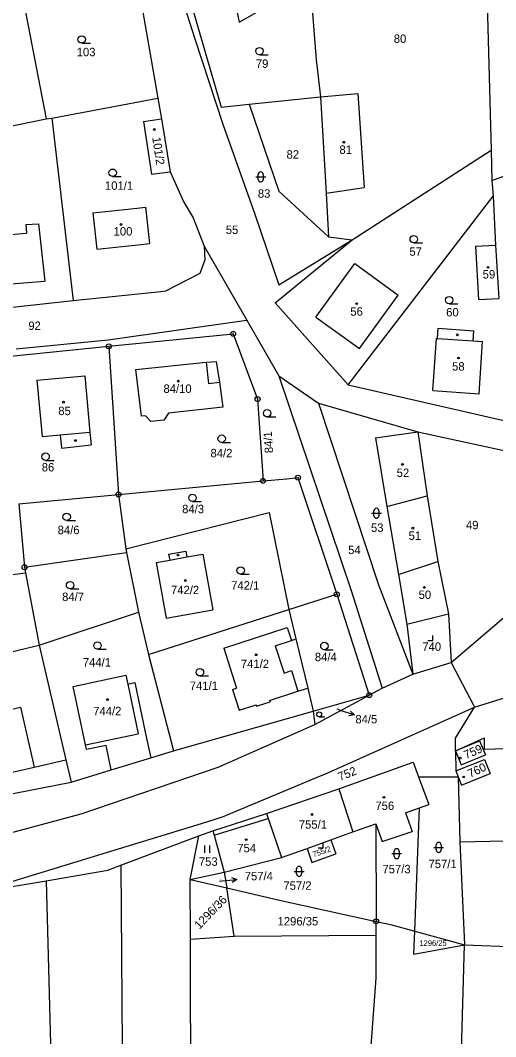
# Model space of a CAD drawing. Extents: x -779596 to -776743, y -1030330 to -1024513.
# Drawn here: x -778185.6 to -778089.5, y -1025062.8 to -1024857.5 of the extents above; entities that cross this region are included whole.
import ezdxf

# ---------------------------------------------------------------- set-up
doc = ezdxf.new("R2010")
doc.units = 0
for name, color, linetype in [('hranice parcel', 7, 'Continuous'), ('hranice vnitřní', 7, 'Continuous'), ('kultura', 7, 'Continuous'), ('Kód', 7, 'Continuous'), ('č_ parcel šipka', 7, 'Continuous'), ('č_pacel stav_', 7, 'Continuous'), ('č_parcel poz_', 7, 'Continuous')]:
    doc.layers.add(name, color=color, linetype=linetype)

msp = doc.modelspace()

# ---------------------------------------------------------------- linework, layer by layer
at = {"layer": 'hranice parcel'}
for points in [[(-778091.74, -1024836.72), (-778090.46, -1024883.74)], [(-778187.93, -1024838.01), (-778180.36, -1024877.36)], [(-778156.76, -1024840.95), (-778150.3, -1024861.21)], [(-778143.11, -1024849.44), (-778141.34, -1024857.84)], [(-778141.34, -1024857.84), (-778129.56, -1024851.15)], [(-778126.92, -1024850.83), (-778125.81, -1024865.47)], [(-778160.91, -1024855.45), (-778157.79, -1024873.21)], [(-778150.99, -1024854.44), (-778145, -1024875.04)], [(-778150.3, -1024861.21), (-778144.64, -1024878.44)], [(-778125.81, -1024865.47), (-778124.94, -1024872.91)], [(-778179.21, -1024877.22), (-778157.79, -1024873.21)], [(-778157.79, -1024873.21), (-778157.06, -1024877.35)], [(-778139.35, -1024874.44), (-778124.94, -1024872.91)], [(-778124.94, -1024872.91), (-778117.34, -1024872.25)], [(-778124.94, -1024872.91), (-778123.8, -1024892.38)], [(-778117.34, -1024872.25), (-778116.08, -1024891.25)], [(-778145, -1024875.04), (-778139.35, -1024874.44)], [(-778139.35, -1024874.44), (-778133.3, -1024892.02)], [(-778200.17, -1024881.44), (-778180.36, -1024877.36)], [(-778180.36, -1024877.36), (-778179.21, -1024877.22)], [(-778179.21, -1024877.22), (-778174.88, -1024914.1)], [(-778160.66, -1024877.95), (-778157.06, -1024877.35)], [(-778160.66, -1024877.95), (-778159.06, -1024888.53)], [(-778157.06, -1024877.35), (-778155.28, -1024888.07)], [(-778144.64, -1024878.44), (-778138.18, -1024896.63)], [(-778118.52, -1024901.85), (-778090.46, -1024883.74)], [(-778090.46, -1024883.74), (-778090.29, -1024889.82)], [(-778090.29, -1024889.82), (-778074.2, -1024884)], [(-778159.06, -1024888.53), (-778155.28, -1024888.07)], [(-778155.28, -1024888.07), (-778152.54, -1024894.21)], [(-778090.29, -1024889.82), (-778090.05, -1024892.99)], [(-778133.3, -1024892.02), (-778123.28, -1024901.22)], [(-778123.8, -1024892.38), (-778116.08, -1024891.25)], [(-778123.8, -1024892.38), (-778123.28, -1024901.22)], [(-778152.54, -1024894.21), (-778150.62, -1024897.36)], [(-778119.3, -1024931.13), (-778090.05, -1024892.99)], [(-778090.05, -1024892.99), (-778089.57, -1024902.87)], [(-778170.92, -1024896.37), (-778161.93, -1024895.39)], [(-778170.92, -1024896.37), (-778170.12, -1024903.72)], [(-778161.93, -1024895.39), (-778160.28, -1024895.21)], [(-778160.28, -1024895.21), (-778159.49, -1024902.57)], [(-778138.18, -1024896.63), (-778133.35, -1024910.93)], [(-778184.42, -1024898.72), (-778181.87, -1024898.56)], [(-778184.42, -1024898.72), (-778184.29, -1024900.49)], [(-778181.87, -1024898.56), (-778180.62, -1024910.17)], [(-778150.62, -1024897.36), (-778148.41, -1024903.12)], [(-778193.8, -1024901.26), (-778184.29, -1024900.49)], [(-778170.12, -1024903.72), (-778161.13, -1024902.74)], [(-778161.13, -1024902.74), (-778159.49, -1024902.57)], [(-778134.1, -1024914.57), (-778118.52, -1024901.85)], [(-778133.35, -1024910.93), (-778118.52, -1024901.85)], [(-778123.28, -1024901.22), (-778118.52, -1024901.85)], [(-778093.62, -1024903.12), (-778089.57, -1024902.87)], [(-778089.57, -1024902.87), (-778088.9, -1024913.65)], [(-778148.41, -1024903.12), (-778139.8, -1024918.03)], [(-778148.41, -1024903.12), (-778148.29, -1024906)], [(-778093.62, -1024903.12), (-778092.96, -1024913.9)], [(-778149.21, -1024908.52), (-778148.29, -1024906)], [(-778125.84, -1024917.43), (-778118.01, -1024906.61)], [(-778118.01, -1024906.61), (-778109.22, -1024912.97)], [(-778156.15, -1024912.15), (-778149.21, -1024908.52)], [(-778192.67, -1024911.14), (-778180.62, -1024910.17)], [(-778174.88, -1024914.1), (-778159.12, -1024912.45)], [(-778159.12, -1024912.45), (-778157.19, -1024912.26)], [(-778157.19, -1024912.26), (-778156.15, -1024912.15)], [(-778117.05, -1024923.79), (-778109.22, -1024912.97)], [(-778197.06, -1024916.48), (-778174.88, -1024914.1)], [(-778134.1, -1024914.57), (-778119.3, -1024931.13)], [(-778092.96, -1024913.9), (-778088.9, -1024913.65)], [(-778167.81, -1024922.02), (-778140.35, -1024918.11)], [(-778140.35, -1024918.11), (-778139.8, -1024918.03)], [(-778139.8, -1024918.03), (-778133.3, -1024929.3)], [(-778125.84, -1024917.43), (-778117.05, -1024923.79)], [(-778167.67, -1024923.32), (-778142.57, -1024920.8)], [(-778142.57, -1024920.8), (-778137.62, -1024933.98)], [(-778101.29, -1024921.75), (-778101.15, -1024919.68)], [(-778101.15, -1024919.68), (-778093.95, -1024920.22)], [(-778094.09, -1024922.25), (-778093.95, -1024920.22)], [(-778187.57, -1024925.32), (-778167.67, -1024923.32)], [(-778186.38, -1024923.83), (-778167.81, -1024922.02)], [(-778167.67, -1024923.32), (-778165.74, -1024953.24)], [(-778102.21, -1024932.25), (-778101.49, -1024921.74)], [(-778101.49, -1024921.74), (-778101.29, -1024921.75)], [(-778094.09, -1024922.25), (-778092.16, -1024922.38)], [(-778092.88, -1024932.89), (-778092.16, -1024922.38)], [(-778162.25, -1024928.04), (-778148, -1024926.51)], [(-778148, -1024926.51), (-778145.96, -1024926.41)], [(-778145.96, -1024926.41), (-778145.32, -1024930.56)], [(-778182.21, -1024930.16), (-778172.55, -1024929.26)], [(-778172.55, -1024929.26), (-778171.5, -1024940.65)], [(-778161.1, -1024937.44), (-778162.25, -1024928.04)], [(-778133.3, -1024929.3), (-778125.29, -1024934.81)], [(-778133.3, -1024929.3), (-778118.73, -1024972.64)], [(-778182.21, -1024930.16), (-778181.15, -1024941.54)], [(-778145.32, -1024930.56), (-778144.66, -1024935.59)], [(-778119.3, -1024931.13), (-778087.28, -1024938.46)], [(-778102.21, -1024932.25), (-778092.88, -1024932.89)], [(-778144.66, -1024935.59), (-778155.62, -1024936.85)], [(-778137.62, -1024933.98), (-778136.53, -1024950.51)], [(-778125.29, -1024934.81), (-778113.21, -1024971.52)], [(-778125.29, -1024934.81), (-778105.25, -1024940.59)], [(-778160.25, -1024937.35), (-778161.1, -1024937.44)], [(-778159.17, -1024938.53), (-778160.25, -1024937.35)], [(-778155.62, -1024936.85), (-778156.58, -1024938.23)], [(-778156.58, -1024938.23), (-778159.17, -1024938.53)], [(-778181.15, -1024941.54), (-778177.51, -1024941.21)], [(-778177.51, -1024941.21), (-778177.25, -1024943.91)], [(-778171.5, -1024940.65), (-778171.26, -1024943.23)], [(-778113.83, -1024941.84), (-778105.25, -1024940.59)], [(-778113.83, -1024941.84), (-778111.48, -1024955.65)], [(-778105.25, -1024940.59), (-778083.52, -1024945.33)], [(-778105.25, -1024940.59), (-778103.39, -1024953.5)], [(-778177.25, -1024943.91), (-778171.26, -1024943.23)], [(-778136.53, -1024950.51), (-778131.74, -1024950.06)], [(-778131.74, -1024950.06), (-778129.47, -1024949.85)], [(-778129.47, -1024949.85), (-778121.63, -1024973.41)], [(-778165.74, -1024953.24), (-778136.53, -1024950.51)], [(-778185.85, -1024955.12), (-778165.74, -1024953.24)], [(-778165.74, -1024953.24), (-778164.25, -1024964.25)], [(-778111.48, -1024955.65), (-778103.39, -1024953.5)], [(-778103.39, -1024953.5), (-778101.19, -1024966.77)], [(-778185.85, -1024955.12), (-778184.71, -1024967.95)], [(-778111.48, -1024955.65), (-778109.14, -1024969.41)], [(-778164.25, -1024964.25), (-778135.3, -1024956.9)], [(-778135.3, -1024956.9), (-778131.29, -1024976.49)], [(-778164.25, -1024964.25), (-778164.11, -1024964.94)], [(-778184.71, -1024967.95), (-778164.11, -1024964.94)], [(-778164.11, -1024964.94), (-778161.69, -1024977.04)], [(-778158.14, -1024966.99), (-778155.38, -1024966.49)], [(-778155.6, -1024965.31), (-778152.1, -1024964.68)], [(-778155.6, -1024965.31), (-778155.38, -1024966.49)], [(-778152.1, -1024964.68), (-778151.89, -1024965.86)], [(-778151.89, -1024965.86), (-778148.69, -1024965.29)], [(-778148.69, -1024965.29), (-778146.67, -1024976.56)], [(-778184.71, -1024967.95), (-778184.51, -1024969.09)], [(-778158.14, -1024966.99), (-778156.11, -1024978.26)], [(-778109.14, -1024969.41), (-778101.19, -1024966.77)], [(-778101.19, -1024966.77), (-778099.04, -1024977.33)], [(-778204.28, -1024971.61), (-778184.51, -1024969.09)], [(-778184.51, -1024969.09), (-778181.75, -1024983.7)], [(-778109.14, -1024969.41), (-778107.48, -1024979.43)], [(-778118.73, -1024972.64), (-778112.47, -1024992.39)], [(-778113.21, -1024971.52), (-778106.27, -1024989.55)], [(-778131.29, -1024976.49), (-778121.63, -1024973.41)], [(-778121.63, -1024973.41), (-778115.06, -1024993.78)], [(-778098.5, -1024987.2), (-778081.81, -1024972.89)], [(-778159.64, -1024985.6), (-778131.29, -1024976.49)], [(-778156.11, -1024978.26), (-778146.67, -1024976.56)], [(-778131.29, -1024976.49), (-778129.88, -1024982.42)], [(-778181.75, -1024983.7), (-778161.69, -1024977.04)], [(-778161.69, -1024977.04), (-778159.64, -1024985.6)], [(-778107.48, -1024979.43), (-778099.04, -1024977.33)], [(-778099.04, -1024977.33), (-778098.5, -1024987.2)], [(-778144.43, -1024984.26), (-778131.63, -1024980.09)], [(-778131.63, -1024980.09), (-778130.77, -1024982.71)], [(-778107.48, -1024979.43), (-778106.27, -1024989.55)], [(-778130.77, -1024982.71), (-778129.88, -1024982.42)], [(-778129.88, -1024982.42), (-778127.5, -1024992.37)], [(-778197.09, -1024987.3), (-778181.75, -1024983.7)], [(-778181.75, -1024983.7), (-778176.36, -1025006.82)], [(-778144.43, -1024984.26), (-778141.87, -1024992.37)], [(-778159.64, -1024985.6), (-778154.6, -1025005)], [(-778106.27, -1024989.55), (-778098.5, -1024987.2)], [(-778098.5, -1024987.2), (-778097.61, -1024988.9)], [(-778097.61, -1024988.9), (-778094.06, -1024995.7)], [(-778174.91, -1024992), (-778164.25, -1024989.72)], [(-778164.25, -1024989.72), (-778163.87, -1024991.54)], [(-778112.47, -1024992.39), (-778106.27, -1024989.55)], [(-778172.39, -1025003.8), (-778174.91, -1024992)], [(-778163.87, -1024991.54), (-778162.45, -1024991.24)], [(-778162.45, -1024991.24), (-778160.31, -1025001.26)], [(-778142.7, -1024992.64), (-778141.87, -1024992.37)], [(-778142.7, -1024992.64), (-778141.36, -1024996.81)], [(-778135.19, -1024994.83), (-778129.47, -1024993)], [(-778129.47, -1024993), (-778127.5, -1024992.37)], [(-778127.5, -1024992.37), (-778126.4, -1024997)], [(-778115.06, -1024993.78), (-778112.47, -1024992.39)], [(-778137.83, -1024996), (-778135.1, -1024995.12)], [(-778135.19, -1024994.83), (-778135.1, -1024995.12)], [(-778126.4, -1024997), (-778115.06, -1024993.78)], [(-778126.09, -1024999.71), (-778115.06, -1024993.78)], [(-778093.81, -1024996.18), (-778085.15, -1024993.48)], [(-778194.68, -1024998.37), (-778185.52, -1024996.21)], [(-778185.52, -1024996.21), (-778182.76, -1025008.31)], [(-778154.6, -1025005), (-778126.4, -1024997)], [(-778141.36, -1024996.81), (-778137.93, -1024995.71)], [(-778137.93, -1024995.71), (-778137.83, -1024996)], [(-778126.4, -1024997), (-778126.09, -1024999.71)], [(-778124.04, -1025009.74), (-778093.81, -1024996.18)], [(-778097.64, -1025002.5), (-778093.81, -1024996.18)], [(-778094.06, -1024995.7), (-778093.81, -1024996.18)], [(-778160.31, -1025001.26), (-778159.2, -1025006.42)], [(-778145.58, -1025008.34), (-778126.09, -1024999.71)], [(-778097.67, -1025005), (-778091.8, -1025002.4)], [(-778097.67, -1025005), (-778097.64, -1025002.5)], [(-778097.67, -1025005), (-778092.76, -1025002.99)], [(-778092.76, -1025002.99), (-778091.6, -1025005.82)], [(-778091.8, -1025004.7), (-778091.8, -1025002.4)], [(-778172.17, -1025004.79), (-778172.39, -1025003.8)], [(-778168.25, -1025003.96), (-778172.17, -1025004.79)], [(-778167.21, -1025008.88), (-778168.25, -1025003.96)], [(-778159.2, -1025006.42), (-778154.6, -1025005)], [(-778097.67, -1025005), (-778096.5, -1025007.83)], [(-778097.67, -1025005), (-778097.6, -1025009.08)], [(-778091.8, -1025004.7), (-778085.3, -1025004.5)], [(-778182.76, -1025008.31), (-778176.36, -1025006.82)], [(-778176.36, -1025006.82), (-778175.3, -1025011.37)], [(-778167.21, -1025008.88), (-778159.2, -1025006.42)], [(-778121.24, -1025012.73), (-778106.19, -1025007.32)], [(-778106.19, -1025007.32), (-778105.09, -1025010.29)], [(-778097.6, -1025009.08), (-778091.77, -1025006.76)], [(-778096.5, -1025007.83), (-778091.6, -1025005.82)], [(-778091.77, -1025006.76), (-778090.63, -1025009.63)], [(-778175.3, -1025011.37), (-778167.21, -1025008.88)], [(-778173.29, -1025017.76), (-778145.58, -1025008.34)], [(-778097.6, -1025009.08), (-778097.13, -1025010.25)], [(-778096.46, -1025011.95), (-778090.63, -1025009.63)], [(-778195, -1025015.2), (-778175.3, -1025011.37)], [(-778144.69, -1025018.37), (-778124.91, -1025010.1)], [(-778124.91, -1025010.1), (-778124.04, -1025009.74)], [(-778105.09, -1025010.29), (-778103.23, -1025010.28)], [(-778105.09, -1025010.29), (-778103.02, -1025015.88)], [(-778103.23, -1025010.28), (-778097.13, -1025010.25)], [(-778097.13, -1025010.25), (-778096.46, -1025011.95)], [(-778097.13, -1025010.25), (-778096.77, -1025023.38)], [(-778135.82, -1025017.7), (-778121.24, -1025012.73)], [(-778121.24, -1025012.73), (-778118.35, -1025021.41)], [(-778191.13, -1025022.54), (-778173.29, -1025017.76)], [(-778146.66, -1025021.15), (-778135.82, -1025017.7)], [(-778135.82, -1025017.7), (-778135.48, -1025018.72)], [(-778107.71, -1025017.52), (-778104.93, -1025016.55)], [(-778107.71, -1025017.52), (-778106.37, -1025021.34)], [(-778105.86, -1025041.47), (-778104.93, -1025016.55)], [(-778104.93, -1025016.55), (-778103.02, -1025015.88)], [(-778168.12, -1025025.58), (-778148.96, -1025019.69)], [(-778148.96, -1025019.69), (-778144.69, -1025018.37)], [(-778135.48, -1025018.72), (-778132.81, -1025026.54)], [(-778118.35, -1025021.41), (-778113.74, -1025019.79)], [(-778113.74, -1025019.79), (-778112.46, -1025023.34)], [(-778113.74, -1025019.79), (-778113.69, -1025039.47)], [(-778149.47, -1025022.2), (-778146.66, -1025021.15)], [(-778146.66, -1025021.15), (-778146.4, -1025022.09)], [(-778122.83, -1025022.98), (-778118.35, -1025021.41)], [(-778112.46, -1025023.34), (-778106.37, -1025021.34)], [(-778165.25, -1025028.14), (-778149.47, -1025022.2)], [(-778151.23, -1025031.02), (-778149.47, -1025022.2)], [(-778146.4, -1025022.09), (-778144.36, -1025029.55)], [(-778127.64, -1025024.73), (-778122.83, -1025022.98)], [(-778122.83, -1025022.98), (-778121.79, -1025025.8)], [(-778096.77, -1025023.38), (-778059.83, -1025022.61)], [(-778096.77, -1025023.38), (-778095.84, -1025044.24)], [(-778194.6, -1025033.67), (-778168.12, -1025025.58)], [(-778132.81, -1025026.54), (-778127.64, -1025024.73)], [(-778127.64, -1025024.73), (-778126.65, -1025027.55)], [(-778126.65, -1025027.55), (-778121.79, -1025025.8)], [(-778144.36, -1025029.55), (-778132.81, -1025026.54)], [(-778180.34, -1025031.25), (-778167.86, -1025029.13)], [(-778167.86, -1025029.13), (-778165.25, -1025028.14)], [(-778165.25, -1025028.14), (-778164.66, -1025110.42)], [(-778151.23, -1025031.02), (-778144.36, -1025029.55)], [(-778144.36, -1025029.55), (-778143.86, -1025032.71)], [(-778194.6, -1025033.67), (-778180.34, -1025031.25)], [(-778180.34, -1025031.25), (-778178.9, -1025084.47)], [(-778151.23, -1025031.02), (-778143.86, -1025032.71)], [(-778151.2, -1025043.03), (-778151.23, -1025031.02)], [(-778142.33, -1025042.46), (-778143.86, -1025032.71)], [(-778143.86, -1025032.71), (-778133.18, -1025035.17)], [(-778133.18, -1025035.17), (-778113.69, -1025039.47)], [(-778113.69, -1025039.47), (-778110.79, -1025040.11)], [(-778113.68, -1025042.27), (-778113.69, -1025039.47)], [(-778110.79, -1025040.11), (-778105.86, -1025041.47)], [(-778151.2, -1025043.03), (-778142.33, -1025042.46)], [(-778142.33, -1025042.46), (-778113.68, -1025042.27)], [(-778113.66, -1025050.93), (-778113.68, -1025042.27)], [(-778106.03, -1025046.06), (-778105.86, -1025041.47)], [(-778105.86, -1025041.47), (-778095.84, -1025044.24)], [(-778150.88, -1025178.87), (-778151.2, -1025043.03)], [(-778106.03, -1025046.06), (-778095.84, -1025044.24)], [(-778100.01, -1025191.35), (-778095.84, -1025044.24)], [(-778095.84, -1025044.24), (-778085.23, -1025044.6)], [(-778115.58, -1025076.38), (-778113.66, -1025050.93)]]:
    msp.add_lwpolyline(points, dxfattribs=at)
at = {"layer": 'hranice vnitřní'}
for points in [[(-778101.29, -1024921.75), (-778094.09, -1024922.25)], [(-778148, -1024926.51), (-778147.51, -1024930.82)], [(-778147.51, -1024930.82), (-778145.32, -1024930.56)], [(-778177.51, -1024941.21), (-778171.5, -1024940.65)], [(-778155.38, -1024966.49), (-778151.89, -1024965.86)], [(-778134.08, -1024983.8), (-778130.77, -1024982.71)], [(-778134.08, -1024983.8), (-778132.28, -1024989.31)], [(-778132.28, -1024989.31), (-778130.8, -1024988.83)], [(-778130.8, -1024988.83), (-778129.47, -1024993)], [(-778163.87, -1024991.54), (-778161.72, -1025001.57)], [(-778172.39, -1025003.8), (-778161.72, -1025001.57)], [(-778191.92, -1025010.44), (-778182.76, -1025008.31)], [(-778146.4, -1025022.09), (-778135.48, -1025018.72)]]:
    msp.add_lwpolyline(points, dxfattribs=at)
at = {"layer": 'kultura'}
for points in [[(-778173.16, -1024862.11), (-778171.41, -1024862.11)], [(-778137.23, -1024864.45), (-778135.48, -1024864.45)], [(-778166.91, -1024889.02), (-778165.16, -1024889.02)], [(-778137.99, -1024889.11), (-778135.99, -1024889.11)], [(-778137.49, -1024889.61), (-778137.49, -1024888.61)], [(-778136.49, -1024888.61), (-778136.49, -1024889.61)], [(-778106.08, -1024902.44), (-778104.33, -1024902.44)], [(-778098.93, -1024914.74), (-778097.18, -1024914.74)], [(-778135.69, -1024937.6), (-778133.94, -1024937.6)], [(-778144.88, -1024942.73), (-778143.13, -1024942.73)], [(-778180.45, -1024946.37), (-778178.7, -1024946.37)], [(-778150.79, -1024954.67), (-778149.04, -1024954.67)], [(-778114.61, -1024957.04), (-778112.61, -1024957.04)], [(-778114.11, -1024957.54), (-778114.11, -1024956.54)], [(-778113.11, -1024956.54), (-778113.11, -1024957.54)], [(-778176.19, -1024958.53), (-778174.44, -1024958.53)], [(-778141.05, -1024969.36), (-778139.3, -1024969.36)], [(-778175.51, -1024972.33), (-778173.76, -1024972.33)], [(-778103.2, -1024982.72), (-778102.2, -1024982.72), (-778102.2, -1024981.72)], [(-778169.96, -1024984.51), (-778168.21, -1024984.51)], [(-778124.13, -1024984.6), (-778122.38, -1024984.6)], [(-778149.27, -1024989.91), (-778147.52, -1024989.91)], [(-778125.19, -1024998.16), (-778124.017, -1024998.16)], [(-778125.4, -1025024.61), (-778124.4, -1025024.61), (-778124.4, -1025023.61)], [(-778148.287, -1025025.615), (-778148.287, -1025024.115)], [(-778147.253, -1025025.615), (-778147.253, -1025024.115)], [(-778110.52, -1025025.79), (-778108.52, -1025025.79)], [(-778110.02, -1025026.29), (-778110.02, -1025025.29)], [(-778109.02, -1025025.29), (-778109.02, -1025026.29)], [(-778102.05, -1025024.53), (-778100.05, -1025024.53)], [(-778101.55, -1025025.03), (-778101.55, -1025024.03)], [(-778100.55, -1025024.03), (-778100.55, -1025025.03)], [(-778130.24, -1025029.38), (-778128.24, -1025029.38)], [(-778129.74, -1025029.88), (-778129.74, -1025028.88)], [(-778128.74, -1025028.88), (-778128.74, -1025029.88)]]:
    msp.add_lwpolyline(points, dxfattribs=at)
for centre, radius in [((-778173.16, -1024861.36), 0.75), ((-778137.23, -1024863.7), 0.75), ((-778158.49, -1024879.53), 0.175), ((-778120.21, -1024882.1), 0.175), ((-778166.91, -1024888.27), 0.75), ((-778165.22, -1024898.72), 0.175), ((-778106.08, -1024901.69), 0.75), ((-778091.08, -1024907.37), 0.175), ((-778117.6, -1024914.72), 0.175), ((-778098.93, -1024913.99), 0.75), ((-778097.27, -1024921.01), 0.175), ((-778097.04, -1024925.69), 0.175), ((-778153.63, -1024930.36), 0.175), ((-778176.82, -1024934.61), 0.175), ((-778135.69, -1024936.85), 0.75), ((-778144.88, -1024941.98), 0.75), ((-778174.43, -1024942.36), 0.175), ((-778180.45, -1024945.62), 0.75), ((-778108.35, -1024947.18), 0.175), ((-778150.79, -1024953.92), 0.75), ((-778176.19, -1024957.78), 0.75), ((-778106.28, -1024960.05), 0.175), ((-778153.7, -1024965.49), 0.175), ((-778141.05, -1024968.61), 0.75), ((-778152.23, -1024970.62), 0.175), ((-778175.51, -1024971.58), 0.75), ((-778103.93, -1024972.03), 0.175), ((-778169.96, -1024983.76), 0.75), ((-778124.13, -1024983.85), 0.75), ((-778137.89, -1024985.62), 0.175), ((-778149.27, -1024989.16), 0.75), ((-778167.97, -1024994.68), 0.175), ((-778125.189, -1024997.657), 0.503), ((-778096.69, -1025006.51), 0.175), ((-778095.98, -1025010.3), 0.175), ((-778112.11, -1025014.41), 0.175), ((-778126.64, -1025017.89), 0.175), ((-778139.92, -1025022.97), 0.175)]:
    msp.add_circle(centre, radius, dxfattribs=at)
for centre, start, end in [((-778136.99, -1024888.61), 0.101, 180.00143), ((-778136.99, -1024889.61), 180.10243, 0.00286), ((-778113.61, -1024956.54), 0.101, 180.00143), ((-778113.61, -1024957.54), 180.10243, 0.00286), ((-778101.05, -1025024.03), 0.101, 180.00143), ((-778109.52, -1025025.29), 0.101, 180.00143), ((-778101.05, -1025025.03), 180.10243, 0.00286), ((-778109.52, -1025026.29), 180.10243, 0.00286), ((-778129.24, -1025028.88), 0.101, 180.00143), ((-778129.24, -1025029.88), 180.10243, 0.00286)]:
    msp.add_arc(centre, 0.5, start, end, dxfattribs=at)
at = {"layer": 'Kód'}
for centre, radius in [((-778142.57, -1024920.8), 0.5), ((-778142.57, -1024920.8), 0.032), ((-778167.67, -1024923.32), 0.5), ((-778167.67, -1024923.32), 0.032), ((-778137.62, -1024933.98), 0.5), ((-778137.62, -1024933.98), 0.032), ((-778136.53, -1024950.51), 0.5), ((-778129.47, -1024949.85), 0.5), ((-778129.47, -1024949.85), 0.032), ((-778136.53, -1024950.51), 0.032), ((-778165.74, -1024953.24), 0.5), ((-778165.74, -1024953.24), 0.032), ((-778184.71, -1024967.95), 0.5), ((-778184.71, -1024967.95), 0.032), ((-778121.63, -1024973.41), 0.5), ((-778121.63, -1024973.41), 0.032), ((-778115.06, -1024993.78), 0.5), ((-778115.06, -1024993.78), 0.032), ((-778113.69, -1025039.47), 0.5), ((-778113.69, -1025039.47), 0.032)]:
    msp.add_circle(centre, radius, dxfattribs=at)
at = {"layer": 'č_ parcel šipka'}
for points in [[(-778121.63, -1024996.57), (-778120.91, -1024996.82)], [(-778120.91, -1024996.82), (-778118.071, -1024997.786)], [(-778118.856, -1024996.991), (-778118.071, -1024997.786), (-778119.178, -1024997.937)], [(-778145.33, -1025031.37), (-778144.81, -1025031.31)], [(-778144.81, -1025031.31), (-778141.827, -1025030.992)], [(-778142.875, -1025030.601), (-778141.827, -1025030.992), (-778142.769, -1025031.594)]]:
    msp.add_lwpolyline(points, dxfattribs=at)

# ---------------------------------------------------------------- texts
for s, p in [('84/5', (-778117.87, -1024999.48)), ('757/4', (-778140.223, -1025031.18))]:
    msp.add_text(s, height=1.7, dxfattribs=at).set_placement(p)
at = {"layer": 'č_pacel stav_'}
for s, height, rotation, p in [('101/2', 1.7, 278.80222, (-778158.932, -1024881.187)), ('759', 1.7, 24.00019, (-778095.489, -1025006.736)), ('760', 1.7, 25.3002, (-778094.675, -1025010.524)), ('755/2', 1.14, 19.00015, (-778126.307, -1025026.546))]:
    msp.add_text(s, height=height, rotation=rotation, dxfattribs=at).set_placement(p)
for s, p in [('81', (-778121.09, -1024884.46)), ('100', (-778166.71, -1024900.95)), ('59', (-778092.15, -1024909.63)), ('56', (-778118.89, -1024917.15)), ('58', (-778098.33, -1024928.23)), ('84/10', (-778156.643, -1024932.73)), ('85', (-778177.89, -1024937.22)), ('52', (-778109.52, -1024949.71)), ('51', (-778107.12, -1024962.42)), ('742/2', (-778155.12, -1024973.38)), ('50', (-778105.09, -1024974.35)), ('740', (-778104.34, -1024984.83)), ('741/2', (-778141, -1024988.3)), ('744/2', (-778170.833, -1024997.84)), ('756', (-778113.82, -1025016.97)), ('755/1', (-778129.29, -1025020.75)), ('754', (-778141.73, -1025025.52))]:
    msp.add_text(s, height=1.7, dxfattribs=at).set_placement(p)
at = {"layer": 'č_parcel poz_'}
for s, height, p in [('80', 1.7, (-778110.11, -1024862.04)), ('103', 1.7, (-778174.17, -1024864.74)), ('79', 1.7, (-778137.97, -1024867.08)), ('82', 1.7, (-778131.78, -1024885.42)), ('101/1', 1.7, (-778168.46, -1024891.72)), ('83', 1.7, (-778137.57, -1024893.32)), ('55', 1.7, (-778144.05, -1024900.64)), ('57', 1.7, (-778106.95, -1024905.03)), ('60', 1.7, (-778099.52, -1024917.29)), ('92', 1.7, (-778183.95, -1024920.02)), ('84/2', 1.7, (-778147.14, -1024945.74)), ('86', 1.7, (-778181.23, -1024948.6)), ('84/3', 1.7, (-778152.87, -1024957.03)), ('84/6', 1.7, (-778178.02, -1024961.27)), ('53', 1.7, (-778114.71, -1024960.8)), ('49', 1.7, (-778095.53, -1024960.27)), ('54', 1.7, (-778119.33, -1024965.29)), ('742/1', 1.7, (-778142.96, -1024972.46)), ('84/7', 1.7, (-778177.12, -1024974.77)), ('744/1', 1.7, (-778172.933, -1024988)), ('84/4', 1.7, (-778126.05, -1024986.91)), ('741/1', 1.7, (-778151.32, -1024992.73)), ('84/5', 0.1, (-778121.43, -1024996.37)), ('753', 1.7, (-778149.49, -1025028.24)), ('757/3', 1.7, (-778112.4, -1025029.76)), ('757/1', 1.7, (-778103.09, -1025028.71)), ('757/4', 0.1, (-778145.296, -1025031.17)), ('757/2', 1.7, (-778132.41, -1025033.09)), ('1296/35', 1.7, (-778133.586, -1025040.29)), ('1296/25', 1.14, (-778104.93, -1025044.42))]:
    msp.add_text(s, height=height, dxfattribs=at).set_placement(p)
for s, rotation, p in [('84/1', 93.90075, (-778134.463, -1024944.845)), ('752', 21.80017, (-778120.969, -1025011.131)), ('1296/36', 46.00037, (-778149.369, -1025041.16))]:
    msp.add_text(s, height=1.7, rotation=rotation, dxfattribs=at).set_placement(p)

doc.saveas('drawing.dxf')
